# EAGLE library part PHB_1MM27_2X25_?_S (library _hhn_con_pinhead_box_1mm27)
Pin Header Box-Type, 1.27mm/0.5"/50mil Pitch, 2x25 Circuits, single gates in schematic Note: see library description for an important note about THT-version
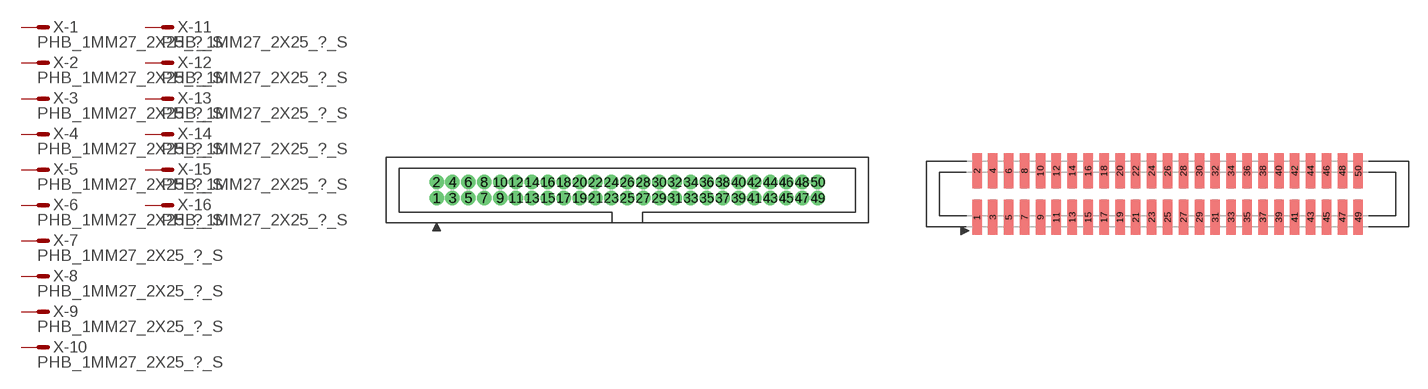
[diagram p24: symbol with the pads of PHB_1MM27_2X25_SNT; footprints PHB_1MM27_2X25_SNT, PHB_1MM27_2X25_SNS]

Designator prefix X; gates -1=M -2=M -3=M -4=M -5=M -6=M -7=M -8=M -9=M -10=M -11=M -12=M -13=M -14=M -15=M -16=M -17=M -18=M -19=M -20=M -21=M -22=M -23=M -24=M -25=M -26=M -27=M -28=M -29=M -30=M -31=M -32=M -33=M -34=M -35=M -36=M -37=M -38=M -39=M -40=M -41=M -42=M -43=M -44=M -45=M -46=M -47=M -48=M -49=M -50=M

## PHB_1MM27_2X25_SNT_S  [PHB_1MM27_2X25_SNT]
1  -1:S  pas
2  -2:S  pas
3  -3:S  pas
4  -4:S  pas
5  -5:S  pas
6  -6:S  pas
7  -7:S  pas
8  -8:S  pas
9  -9:S  pas
10  -10:S  pas
11  -11:S  pas
12  -12:S  pas
13  -13:S  pas
14  -14:S  pas
15  -15:S  pas
16  -16:S  pas
17  -17:S  pas
18  -18:S  pas
19  -19:S  pas
20  -20:S  pas
21  -21:S  pas
22  -22:S  pas
23  -23:S  pas
24  -24:S  pas
25  -25:S  pas
26  -26:S  pas
27  -27:S  pas
28  -28:S  pas
29  -29:S  pas
30  -30:S  pas
31  -31:S  pas
32  -32:S  pas
33  -33:S  pas
34  -34:S  pas
35  -35:S  pas
36  -36:S  pas
37  -37:S  pas
38  -38:S  pas
39  -39:S  pas
40  -40:S  pas
41  -41:S  pas
42  -42:S  pas
43  -43:S  pas
44  -44:S  pas
45  -45:S  pas
46  -46:S  pas
47  -47:S  pas
48  -48:S  pas
49  -49:S  pas
50  -50:S  pas

## PHB_1MM27_2X25_SNS_S  [PHB_1MM27_2X25_SNS]
Pads as for PHB_1MM27_2X25_SNT

## Footprint PHB_1MM27_2X25_SNT (pad centres in mm)
Pin Header Box-Type, 1.27mm Pitch, 2x25 circuits, Straight, No Locking, THT Important Note: Diameter in this lbr is set to a specific value (NOT 'auto' = 0), this is ignored by actual eagle versions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
drill 0.65 pad 1 round: 1 -15.24,-0.635; 2 -15.24,0.635; 3 -13.97,-0.635; 4 -13.97,0.635; 5 -12.7,-0.635; 6 -12.7,0.635; 7 -11.43,-0.635; 8 -11.43,0.635; 9 -10.16,-0.635; 10 -10.16,0.635; 11 -8.89,-0.635; 12 -8.89,0.635; 13 -7.62,-0.635; 14 -7.62,0.635; 15 -6.35,-0.635; 16 -6.35,0.635; 17 -5.08,-0.635; 18 -5.08,0.635; 19 -3.81,-0.635; 20 -3.81,0.635; 21 -2.54,-0.635; 22 -2.54,0.635; 23 -1.27,-0.635; 24 -1.27,0.635; 25 0,-0.635; 26 0,0.635; 27 1.27,-0.635; 28 1.27,0.635; 29 2.54,-0.635; 30 2.54,0.635; 31 3.81,-0.635; 32 3.81,0.635; 33 5.08,-0.635; 34 5.08,0.635; 35 6.35,-0.635; 36 6.35,0.635; 37 7.62,-0.635; 38 7.62,0.635; 39 8.89,-0.635; 40 8.89,0.635; 41 10.16,-0.635; 42 10.16,0.635; 43 11.43,-0.635; 44 11.43,0.635; 45 12.7,-0.635; 46 12.7,0.635; 47 13.97,-0.635; 48 13.97,0.635; 49 15.24,-0.635; 50 15.24,0.635

## Footprint PHB_1MM27_2X25_SNS (pad centres in mm)
Pin Header Box-Type, 1.27mm Pitch, 2x25 circuits, Straight, No Locking, SMT
smd 0.76 x 2.8: 1 -15.24,-1.85; 2 -15.24,1.85; 3 -13.97,-1.85; 4 -13.97,1.85; 5 -12.7,-1.85; 6 -12.7,1.85; 7 -11.43,-1.85; 8 -11.43,1.85; 9 -10.16,-1.85; 10 -10.16,1.85; 11 -8.89,-1.85; 12 -8.89,1.85; 13 -7.62,-1.85; 14 -7.62,1.85; 15 -6.35,-1.85; 16 -6.35,1.85; 17 -5.08,-1.85; 18 -5.08,1.85; 19 -3.81,-1.85; 20 -3.81,1.85; 21 -2.54,-1.85; 22 -2.54,1.85; 23 -1.27,-1.85; 24 -1.27,1.85; 25 0,-1.85; 26 0,1.85; 27 1.27,-1.85; 28 1.27,1.85; 29 2.54,-1.85; 30 2.54,1.85; 31 3.81,-1.85; 32 3.81,1.85; 33 5.08,-1.85; 34 5.08,1.85; 35 6.35,-1.85; 36 6.35,1.85; 37 7.62,-1.85; 38 7.62,1.85; 39 8.89,-1.85; 40 8.89,1.85; 41 10.16,-1.85; 42 10.16,1.85; 43 11.43,-1.85; 44 11.43,1.85; 45 12.7,-1.85; 46 12.7,1.85; 47 13.97,-1.85; 48 13.97,1.85; 49 15.24,-1.85; 50 15.24,1.85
